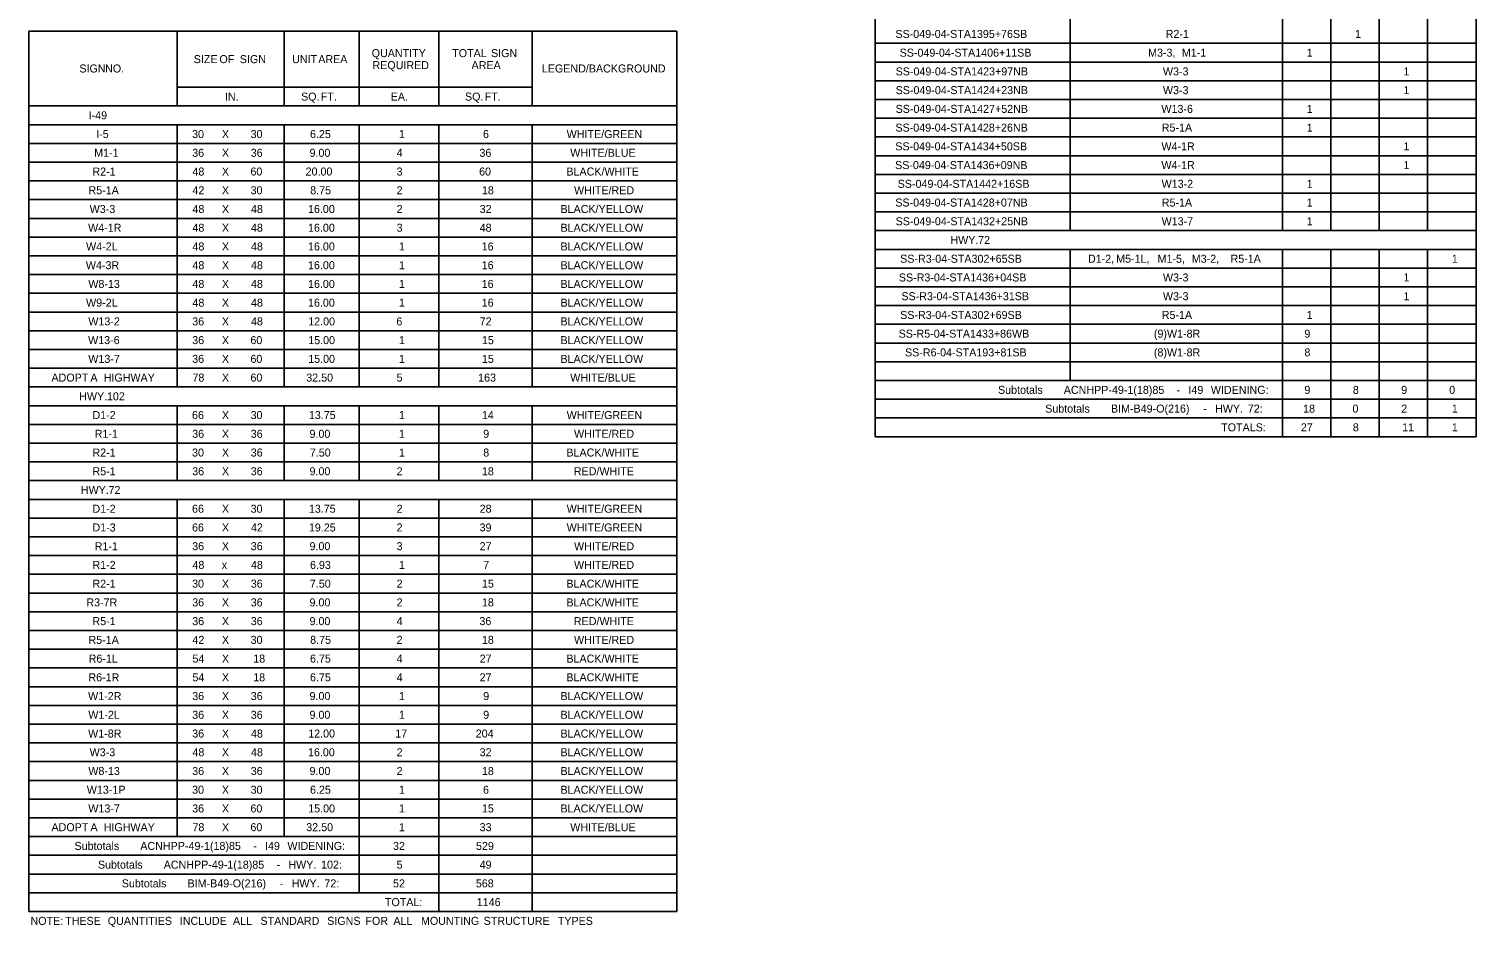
# Model space of a CAD drawing. Extents: x 1226613 to 1228135, y 151309 to 152326.
# Drawn here: x 1226615 to 1227428, y 151322 to 151827 of the extents above; entities that cross this region are included whole.
import ezdxf

# ---------------------------------------------------------------- set-up
doc = ezdxf.new("R2010")
doc.units = 0
doc.layers.add('R_Dimension', color=7, linetype='Continuous')

msp = doc.modelspace()

# ---------------------------------------------------------------- linework, layer by layer
at = {"layer": 'R_Dimension'}
for p, q in [((1227090.5, 151597.36), (1227090.5, 152039.62)), ((1227428.34, 151597.36), (1227428.34, 152039.62)), ((1227200.19, 151713.19), (1227200.19, 151986.97)), ((1227319.53, 151713.19), (1227319.53, 151986.97)), ((1227346.73, 151713.19), (1227346.73, 151986.97)), ((1227373.93, 151713.19), (1227373.93, 151986.97)), ((1227401.13, 151713.19), (1227401.13, 151986.97)), ((1226614.79, 151825.39), (1226978.96, 151825.39)), ((1226614.79, 151330.48), (1226614.79, 151825.39)), ((1226698.16, 151783.27), (1226698.16, 151825.39)), ((1226758.27, 151783.27), (1226758.27, 151825.39)), ((1226800.39, 151783.27), (1226800.39, 151825.39)), ((1226845.14, 151783.27), (1226845.14, 151825.39)), ((1226897.79, 151783.27), (1226897.79, 151825.39)), ((1226978.96, 151330.48), (1226978.96, 151825.39)), ((1227090.5, 151818.49), (1227428.34, 151818.49)), ((1227090.5, 151807.96), (1227428.34, 151807.96)), ((1226698.16, 151793.8), (1226897.79, 151793.8)), ((1227090.5, 151797.43), (1227428.34, 151797.43)), ((1226614.79, 151783.27), (1226978.96, 151783.27)), ((1226897.79, 151783.27), (1226978.96, 151783.27)), ((1227090.5, 151786.9), (1227428.34, 151786.9)), ((1227090.5, 151776.37), (1227428.34, 151776.37)), ((1226614.79, 151772.74), (1226978.96, 151772.74)), ((1226698.16, 151625.32), (1226698.16, 151772.74)), ((1226758.27, 151625.32), (1226758.27, 151772.74)), ((1226800.39, 151625.32), (1226800.39, 151772.74)), ((1226845.14, 151625.32), (1226845.14, 151772.74)), ((1226897.79, 151625.32), (1226897.79, 151772.74)), ((1226614.79, 151762.21), (1226978.96, 151762.21)), ((1227090.5, 151765.84), (1227428.34, 151765.84)), ((1226614.79, 151751.68), (1226978.96, 151751.68)), ((1227090.5, 151755.31), (1227428.34, 151755.31)), ((1227090.5, 151744.78), (1227428.34, 151744.78)), ((1226614.79, 151741.15), (1226978.96, 151741.15)), ((1227090.5, 151734.25), (1227428.34, 151734.25)), ((1226614.79, 151730.62), (1226978.96, 151730.62)), ((1226614.79, 151720.09), (1226978.96, 151720.09)), ((1227090.5, 151723.72), (1227428.34, 151723.72)), ((1226614.79, 151709.56), (1226978.96, 151709.56)), ((1227090.5, 151713.19), (1227428.34, 151713.19)), ((1227090.5, 151702.66), (1227428.34, 151702.66)), ((1227200.19, 151628.95), (1227200.19, 151702.66)), ((1227319.53, 151597.36), (1227319.53, 151702.66)), ((1227346.73, 151597.36), (1227346.73, 151702.66)), ((1227373.93, 151597.36), (1227373.93, 151702.66)), ((1227401.13, 151597.36), (1227401.13, 151702.66)), ((1226614.79, 151699.03), (1226978.96, 151699.03)), ((1226614.79, 151688.5), (1226978.96, 151688.5)), ((1227090.5, 151692.13), (1227428.34, 151692.13)), ((1226614.79, 151677.97), (1226978.96, 151677.97)), ((1227090.5, 151681.6), (1227428.34, 151681.6)), ((1227090.5, 151671.07), (1227428.34, 151671.07)), ((1226614.79, 151667.44), (1226978.96, 151667.44)), ((1227090.5, 151660.54), (1227428.34, 151660.54)), ((1226614.79, 151656.91), (1226978.96, 151656.91)), ((1226614.79, 151646.38), (1226978.96, 151646.38)), ((1227090.5, 151650.01), (1227428.34, 151650.01)), ((1227090.5, 151639.48), (1227428.34, 151639.48)), ((1226614.79, 151635.85), (1226978.96, 151635.85)), ((1227090.5, 151628.95), (1227428.34, 151628.95)), ((1226614.79, 151625.32), (1226978.96, 151625.32)), ((1226614.79, 151614.79), (1226978.96, 151614.79)), ((1226698.16, 151572.67), (1226698.16, 151614.79)), ((1226758.27, 151572.67), (1226758.27, 151614.79)), ((1226800.39, 151572.67), (1226800.39, 151614.79)), ((1226845.14, 151572.67), (1226845.14, 151614.79)), ((1226897.79, 151572.67), (1226897.79, 151614.79)), ((1227090.5, 151618.42), (1227428.34, 151618.42)), ((1226614.79, 151604.26), (1226978.96, 151604.26)), ((1227090.5, 151607.89), (1227428.34, 151607.89)), ((1227090.5, 151597.36), (1227428.34, 151597.36)), ((1226614.79, 151593.73), (1226978.96, 151593.73)), ((1226614.79, 151583.2), (1226978.96, 151583.2)), ((1226614.79, 151572.67), (1226978.96, 151572.67)), ((1226614.79, 151562.14), (1226978.96, 151562.14)), ((1226698.16, 151372.6), (1226698.16, 151562.14)), ((1226758.27, 151372.6), (1226758.27, 151562.14)), ((1226800.39, 151341.01), (1226800.39, 151562.14)), ((1226845.14, 151330.48), (1226845.14, 151562.14)), ((1226897.79, 151330.48), (1226897.79, 151562.14)), ((1226614.79, 151551.61), (1226978.96, 151551.61)), ((1226614.79, 151541.08), (1226978.96, 151541.08)), ((1226614.79, 151530.55), (1226978.96, 151530.55)), ((1226614.79, 151520.02), (1226978.96, 151520.02)), ((1226614.79, 151509.49), (1226978.96, 151509.49)), ((1226614.79, 151498.96), (1226978.96, 151498.96)), ((1226614.79, 151488.43), (1226978.96, 151488.43)), ((1226614.79, 151477.9), (1226978.96, 151477.9)), ((1226614.79, 151467.37), (1226978.96, 151467.37)), ((1226614.79, 151456.84), (1226978.96, 151456.84)), ((1226614.79, 151446.31), (1226978.96, 151446.31)), ((1226614.79, 151435.78), (1226978.96, 151435.78)), ((1226614.79, 151425.25), (1226978.96, 151425.25)), ((1226614.79, 151414.72), (1226978.96, 151414.72)), ((1226614.79, 151404.19), (1226978.96, 151404.19)), ((1226614.79, 151393.66), (1226978.96, 151393.66)), ((1226614.79, 151383.13), (1226978.96, 151383.13)), ((1226614.79, 151372.6), (1226978.96, 151372.6)), ((1226614.79, 151362.07), (1226978.96, 151362.07)), ((1226614.79, 151351.54), (1226978.96, 151351.54)), ((1226614.79, 151341.01), (1226978.96, 151341.01)), ((1226614.79, 151330.48), (1226978.96, 151330.48))]:
    msp.add_line(p, q, dxfattribs=at)

# ---------------------------------------------------------------- texts
for s, p in [('SS-049-04-STA1395+76SB', (1227101.92, 151821.5)), ('R2-1', (1227253.87, 151821.5)), ('1', (1227360.33, 151821.5)), ('QUANTITY', (1226807.49, 151810.72)), ('TOTAL', (1226852.75, 151810.72)), (' SIGN', (1226872.88, 151810.72)), ('SS-049-04-STA1406+11SB', (1227104.29, 151810.97)), ('M3-3,', (1227243.96, 151810.97)), (' M1-1', (1227261.26, 151810.97)), ('1', (1227333.13, 151810.97)), ('SIZE', (1226707.45, 151807.34)), (' OF', (1226720.2, 151807.34)), (' SIGN', (1226731.68, 151807.34)), ('UNIT', (1226762.76, 151807.34)), (' AREA', (1226775.77, 151807.34)), ('REQUIRED', (1226807.93, 151803.97)), ('AREA', (1226863.65, 151803.97)), ('LEGEND/BACKGROUND', (1226903.13, 151802.08)), ('SIGN', (1226643.15, 151802.08)), (' NO.', (1226655.94, 151802.08)), ('SS-049-04-STA1423+97NB', (1227102.03, 151800.44)), ('W3-3', (1227252.31, 151800.44)), ('1', (1227387.53, 151800.44)), ('IN.', (1226724.99, 151786.28)), ('SQ.', (1226767.79, 151786.28)), (' FT.', (1226777.22, 151786.28)), ('EA.', (1226818.19, 151786.28)), ('SQ.', (1226859.93, 151786.28)), (' FT.', (1226869.36, 151786.28)), ('SS-049-04-STA1424+23NB', (1227102.03, 151789.91)), ('W3-3', (1227252.31, 151789.91)), ('1', (1227387.53, 151789.91)), ('SS-049-04-STA1427+52NB', (1227102.03, 151779.38)), ('W13-6', (1227251.44, 151779.38)), ('1', (1227333.13, 151779.38)), ('I-49', (1226648.33, 151775.75)), ('I-5', (1226652.61, 151765.22)), ('30', (1226706.51, 151765.22)), ('X', (1226723.28, 151765.22)), ('30', (1226739.42, 151765.22)), ('6.25', (1226772.81, 151765.22)), ('1', (1226822.76, 151765.22)), ('6', (1226870.06, 151765.22)), ('WHITE/GREEN', (1226917.1, 151765.22)), ('SS-049-04-STA1428+26NB', (1227101.92, 151768.85)), ('R5-1A', (1227251.65, 151768.85)), ('1', (1227333.13, 151768.85)), ('M1-1', (1226651.48, 151754.69)), ('36', (1226706.58, 151754.69)), ('X', (1226723.28, 151754.69)), ('36', (1226739.49, 151754.69)), ('9.00', (1226772.54, 151754.69)), ('4', (1226821.49, 151754.69)), ('36', (1226868.04, 151754.69)), ('WHITE/BLUE', (1226919.1, 151754.69)), ('SS-049-04-STA1434+50SB', (1227101.85, 151758.32)), ('W4-1R', (1227251.44, 151758.32)), ('1', (1227387.53, 151758.32)), ('SS-049-04-STA1436+09NB', (1227101.74, 151747.79)), ('W4-1R', (1227251.44, 151747.79)), ('1', (1227387.53, 151747.79)), ('R2-1', (1226650.49, 151744.16)), ('48', (1226706.71, 151744.16)), ('X', (1226723.28, 151744.16)), ('60', (1226739.31, 151744.16)), ('20.00', (1226770.34, 151744.16)), ('3', (1226821.49, 151744.16)), ('60', (1226867.87, 151744.16)), ('BLACK/WHITE', (1226916.94, 151744.16)), ('SS-049-04-STA1442+16SB', (1227103.19, 151737.26)), ('W13-2', (1227251.56, 151737.26)), ('1', (1227333.13, 151737.26)), ('R5-1A', (1226648.27, 151733.63)), ('42', (1226706.71, 151733.63)), ('X', (1226723.28, 151733.63)), ('30', (1226739.42, 151733.63)), ('8.75', (1226772.91, 151733.63)), ('2', (1226821.49, 151733.63)), ('18', (1226869.44, 151733.63)), ('WHITE/RED', (1226921.24, 151733.63)), ('W3-3', (1226648.93, 151723.1)), ('48', (1226706.71, 151723.1)), ('X', (1226723.28, 151723.1)), ('48', (1226739.61, 151723.1)), ('16.00', (1226771.69, 151723.1)), ('2', (1226821.49, 151723.1)), ('32', (1226868.17, 151723.1)), ('BLACK/YELLOW', (1226913.61, 151723.1)), ('SS-049-04-STA1428+07NB', (1227101.85, 151726.73)), ('R5-1A', (1227251.65, 151726.73)), ('1', (1227333.13, 151726.73)), ('BLACK/YELLOW', (1226913.61, 151712.57)), ('SS-049-04-STA1432+25NB', (1227102.03, 151716.2)), ('W13-7', (1227251.56, 151716.2)), ('1', (1227333.13, 151716.2)), ('W4-1R', (1226648.06, 151712.57)), ('48', (1226706.71, 151712.57)), ('X', (1226723.28, 151712.57)), ('48', (1226739.61, 151712.57)), ('16.00', (1226771.69, 151712.57)), ('3', (1226821.49, 151712.57)), ('48', (1226868.17, 151712.57)), ('HWY.', (1227132.85, 151705.67)), (' 72', (1227146.74, 151705.67)), ('W4-2L', (1226646.91, 151702.04)), ('48', (1226706.71, 151702.04)), ('X', (1226723.28, 151702.04)), ('48', (1226739.61, 151702.04)), ('16.00', (1226771.69, 151702.04)), ('1', (1226822.76, 151702.04)), ('16', (1226869.32, 151702.04)), ('BLACK/YELLOW', (1226913.61, 151702.04)), ('W4-3R', (1226646.79, 151691.51)), ('48', (1226706.71, 151691.51)), ('X', (1226723.28, 151691.51)), ('48', (1226739.61, 151691.51)), ('16.00', (1226771.69, 151691.51)), ('1', (1226822.76, 151691.51)), ('16', (1226869.32, 151691.51)), ('BLACK/YELLOW', (1226913.61, 151691.51)), ('SS-R3-04-STA302+65SB', (1227104.58, 151695.14)), ('D1-2,', (1227210.16, 151695.14)), (' M5-1L,', (1227224.33, 151695.14)), (' M1-5,', (1227247.61, 151695.14)), (' M3-2,', (1227266.85, 151695.14)), (' R5-1A', (1227288.65, 151695.14)), ('1', (1227414.73, 151695.14)), ('W8-13', (1226648.18, 151680.98)), ('48', (1226706.71, 151680.98)), ('X', (1226723.28, 151680.98)), ('48', (1226739.61, 151680.98)), ('16.00', (1226771.69, 151680.98)), ('1', (1226822.76, 151680.98)), ('16', (1226869.32, 151680.98)), ('BLACK/YELLOW', (1226913.61, 151680.98)), ('SS-R3-04-STA1436+04SB', (1227103.83, 151684.61)), ('W3-3', (1227252.31, 151684.61)), ('1', (1227387.53, 151684.61)), ('SS-R3-04-STA1436+31SB', (1227105.29, 151674.08)), ('W3-3', (1227252.31, 151674.08)), ('1', (1227387.53, 151674.08)), ('W9-2L', (1226646.91, 151670.45)), ('48', (1226706.71, 151670.45)), ('X', (1226723.28, 151670.45)), ('48', (1226739.61, 151670.45)), ('16.00', (1226771.69, 151670.45)), ('1', (1226822.76, 151670.45)), ('16', (1226869.32, 151670.45)), ('BLACK/YELLOW', (1226913.61, 151670.45)), ('W13-2', (1226648.18, 151659.92)), ('36', (1226706.58, 151659.92)), ('X', (1226723.28, 151659.92)), ('48', (1226739.61, 151659.92)), ('12.00', (1226771.8, 151659.92)), ('6', (1226821.36, 151659.92)), ('72', (1226868.17, 151659.92)), ('BLACK/YELLOW', (1226913.61, 151659.92)), ('SS-R3-04-STA302+69SB', (1227104.58, 151663.55)), ('R5-1A', (1227251.65, 151663.55)), ('1', (1227333.13, 151663.55)), ('W13-6', (1226648.06, 151649.39)), ('36', (1226706.58, 151649.39)), ('X', (1226723.28, 151649.39)), ('60', (1226739.31, 151649.39)), ('15.00', (1226771.8, 151649.39)), ('1', (1226822.76, 151649.39)), ('15', (1226869.44, 151649.39)), ('BLACK/YELLOW', (1226913.61, 151649.39)), ('SS-R5-04-STA1433+86WB', (1227103.73, 151653.02)), ('(9)W1-8R', (1227247.22, 151653.02)), ('9', (1227331.83, 151653.02)), ('SS-R6-04-STA193+81SB', (1227107.3, 151642.49)), ('(8)W1-8R', (1227247.22, 151642.49)), ('8', (1227331.85, 151642.49)), ('W13-7', (1226648.18, 151638.86)), ('36', (1226706.58, 151638.86)), ('X', (1226723.28, 151638.86)), ('60', (1226739.31, 151638.86)), ('15.00', (1226771.8, 151638.86)), ('1', (1226822.76, 151638.86)), ('15', (1226869.44, 151638.86)), ('BLACK/YELLOW', (1226913.61, 151638.86)), ('ADOPT', (1226627.46, 151628.33)), (' A', (1226647.69, 151628.33)), (' HIGHWAY', (1226655.13, 151628.33)), ('78', (1226706.71, 151628.33)), ('X', (1226723.28, 151628.33)), ('60', (1226739.31, 151628.33)), ('32.50', (1226770.7, 151628.33)), ('5', (1226821.49, 151628.33)), ('163', (1226867.32, 151628.33)), ('WHITE/BLUE', (1226919.1, 151628.33)), ('HWY.', (1226643.06, 151617.8)), (' 102', (1226656.95, 151617.8)), ('Subtotals', (1227159.59, 151621.43)), (' ACNHPP-49-1(18)85', (1227194.88, 151621.43)), (' -', (1227258.27, 151621.43)), (' I49', (1227264.96, 151621.43)), (' WIDENING:', (1227277.58, 151621.43)), ('9', (1227331.83, 151621.43)), ('8', (1227359.05, 151621.43)), ('9', (1227386.24, 151621.43)), ('0', (1227413.26, 151621.43)), ('D1-2', (1226650.49, 151607.27)), ('66', (1226706.48, 151607.27)), ('X', (1226723.28, 151607.27)), ('30', (1226739.42, 151607.27)), ('13.75', (1226772.17, 151607.27)), ('1', (1226822.76, 151607.27)), ('14', (1226869.44, 151607.27)), ('WHITE/GREEN', (1226917.1, 151607.27)), ('Subtotals', (1227186.12, 151610.9)), (' BIM-B49-O(216)', (1227221.42, 151610.9)), (' -', (1227273.25, 151610.9)), (' HWY.', (1227279.95, 151610.9)), (' 72:', (1227298.34, 151610.9)), ('18', (1227331.11, 151610.9)), ('0', (1227358.86, 151610.9)), ('2', (1227386.26, 151610.9)), ('1', (1227414.73, 151610.9)), ('TOTALS:', (1227285.05, 151600.37)), ('27', (1227329.83, 151600.37)), ('8', (1227359.05, 151600.37)), ('11', (1227386.79, 151600.37)), ('1', (1227414.73, 151600.37)), ('R1-1', (1226651.76, 151596.74)), ('36', (1226706.58, 151596.74)), ('X', (1226723.28, 151596.74)), ('36', (1226739.49, 151596.74)), ('9.00', (1226772.54, 151596.74)), ('1', (1226822.76, 151596.74)), ('9', (1226870.17, 151596.74)), ('WHITE/RED', (1226921.24, 151596.74)), ('R2-1', (1226650.49, 151586.21)), ('30', (1226706.51, 151586.21)), ('X', (1226723.28, 151586.21)), ('36', (1226739.49, 151586.21)), ('7.50', (1226772.72, 151586.21)), ('1', (1226822.76, 151586.21)), ('8', (1226870.19, 151586.21)), ('BLACK/WHITE', (1226916.94, 151586.21)), ('R5-1', (1226650.49, 151575.68)), ('36', (1226706.58, 151575.68)), ('X', (1226723.28, 151575.68)), ('36', (1226739.49, 151575.68)), ('9.00', (1226772.54, 151575.68)), ('2', (1226821.49, 151575.68)), ('18', (1226869.44, 151575.68)), ('RED/WHITE', (1226921.15, 151575.68)), ('HWY.', (1226643.99, 151565.15)), (' 72', (1226657.88, 151565.15)), ('D1-2', (1226650.49, 151554.62)), ('66', (1226706.48, 151554.62)), ('X', (1226723.28, 151554.62)), ('30', (1226739.42, 151554.62)), ('13.75', (1226772.17, 151554.62)), ('2', (1226821.49, 151554.62)), ('28', (1226868.17, 151554.62)), ('WHITE/GREEN', (1226917.1, 151554.62)), ('D1-3', (1226650.49, 151544.09)), ('66', (1226706.48, 151544.09)), ('X', (1226723.28, 151544.09)), ('42', (1226739.61, 151544.09)), ('19.25', (1226772.17, 151544.09)), ('2', (1226821.49, 151544.09)), ('39', (1226868.15, 151544.09)), ('WHITE/GREEN', (1226917.1, 151544.09)), ('WHITE/RED', (1226921.24, 151533.56)), ('R1-1', (1226651.76, 151533.56)), ('36', (1226706.58, 151533.56)), ('X', (1226723.28, 151533.56)), ('36', (1226739.49, 151533.56)), ('9.00', (1226772.54, 151533.56)), ('3', (1226821.49, 151533.56)), ('27', (1226868.17, 151533.56)), ('R1-2', (1226650.49, 151523.03)), ('48', (1226706.71, 151523.03)), ('x', (1226723.21, 151523.03)), ('48', (1226739.61, 151523.03)), ('6.93', (1226772.81, 151523.03)), ('1', (1226822.76, 151523.03)), ('7', (1226870.19, 151523.03)), ('WHITE/RED', (1226921.24, 151523.03)), ('R2-1', (1226650.49, 151512.5)), ('30', (1226706.51, 151512.5)), ('X', (1226723.28, 151512.5)), ('36', (1226739.49, 151512.5)), ('7.50', (1226772.72, 151512.5)), ('2', (1226821.49, 151512.5)), ('15', (1226869.44, 151512.5)), ('BLACK/WHITE', (1226916.94, 151512.5)), ('R3-7R', (1226647.07, 151501.97)), ('36', (1226706.58, 151501.97)), ('X', (1226723.28, 151501.97)), ('36', (1226739.49, 151501.97)), ('9.00', (1226772.54, 151501.97)), ('2', (1226821.49, 151501.97)), ('18', (1226869.44, 151501.97)), ('BLACK/WHITE', (1226916.94, 151501.97)), ('R5-1', (1226650.49, 151491.44)), ('36', (1226706.58, 151491.44)), ('X', (1226723.28, 151491.44)), ('36', (1226739.49, 151491.44)), ('9.00', (1226772.54, 151491.44)), ('4', (1226821.49, 151491.44)), ('36', (1226868.04, 151491.44)), ('RED/WHITE', (1226921.15, 151491.44)), ('R5-1A', (1226648.27, 151480.91)), ('42', (1226706.71, 151480.91)), ('X', (1226723.28, 151480.91)), ('30', (1226739.42, 151480.91)), ('8.75', (1226772.91, 151480.91)), ('2', (1226821.49, 151480.91)), ('18', (1226869.44, 151480.91)), ('WHITE/RED', (1226921.24, 151480.91)), ('R6-1L', (1226648.36, 151470.38)), ('54', (1226706.71, 151470.38)), ('X', (1226723.28, 151470.38)), ('18', (1226740.89, 151470.38)), ('6.75', (1226772.81, 151470.38)), ('4', (1226821.49, 151470.38)), ('27', (1226868.17, 151470.38)), ('BLACK/WHITE', (1226916.94, 151470.38)), ('R6-1R', (1226648.24, 151459.85)), ('54', (1226706.71, 151459.85)), ('X', (1226723.28, 151459.85)), ('18', (1226740.89, 151459.85)), ('6.75', (1226772.81, 151459.85)), ('4', (1226821.49, 151459.85)), ('27', (1226868.17, 151459.85)), ('BLACK/WHITE', (1226916.94, 151459.85)), ('W1-2R', (1226648.06, 151449.32)), ('36', (1226706.58, 151449.32)), ('X', (1226723.28, 151449.32)), ('36', (1226739.49, 151449.32)), ('9.00', (1226772.54, 151449.32)), ('1', (1226822.76, 151449.32)), ('9', (1226870.17, 151449.32)), ('BLACK/YELLOW', (1226913.61, 151449.32)), ('W1-2L', (1226648.18, 151438.79)), ('36', (1226706.58, 151438.79)), ('X', (1226723.28, 151438.79)), ('36', (1226739.49, 151438.79)), ('9.00', (1226772.54, 151438.79)), ('1', (1226822.76, 151438.79)), ('9', (1226870.17, 151438.79)), ('BLACK/YELLOW', (1226913.61, 151438.79)), ('W1-8R', (1226648.06, 151428.26)), ('36', (1226706.58, 151428.26)), ('X', (1226723.28, 151428.26)), ('48', (1226739.61, 151428.26)), ('12.00', (1226771.8, 151428.26)), ('17', (1226820.74, 151428.26)), ('204', (1226865.97, 151428.26)), ('BLACK/YELLOW', (1226913.61, 151428.26)), ('W3-3', (1226648.93, 151417.73)), ('48', (1226706.71, 151417.73)), ('X', (1226723.28, 151417.73)), ('48', (1226739.61, 151417.73)), ('16.00', (1226771.69, 151417.73)), ('2', (1226821.49, 151417.73)), ('32', (1226868.17, 151417.73)), ('BLACK/YELLOW', (1226913.61, 151417.73)), ('W8-13', (1226648.18, 151407.2)), ('36', (1226706.58, 151407.2)), ('X', (1226723.28, 151407.2)), ('36', (1226739.49, 151407.2)), ('9.00', (1226772.54, 151407.2)), ('2', (1226821.49, 151407.2)), ('18', (1226869.44, 151407.2)), ('BLACK/YELLOW', (1226913.61, 151407.2)), ('W13-1P', (1226647.32, 151396.67)), ('30', (1226706.51, 151396.67)), ('X', (1226723.28, 151396.67)), ('30', (1226739.42, 151396.67)), ('6.25', (1226772.81, 151396.67)), ('1', (1226822.76, 151396.67)), ('6', (1226870.06, 151396.67)), ('BLACK/YELLOW', (1226913.61, 151396.67)), ('W13-7', (1226648.18, 151386.14)), ('36', (1226706.58, 151386.14)), ('X', (1226723.28, 151386.14)), ('60', (1226739.31, 151386.14)), ('15.00', (1226771.8, 151386.14)), ('1', (1226822.76, 151386.14)), ('15', (1226869.44, 151386.14)), ('BLACK/YELLOW', (1226913.61, 151386.14)), ('ADOPT', (1226627.46, 151375.61)), (' A', (1226647.69, 151375.61)), (' HIGHWAY', (1226655.13, 151375.61)), ('78', (1226706.71, 151375.61)), ('X', (1226723.28, 151375.61)), ('60', (1226739.31, 151375.61)), ('32.50', (1226770.7, 151375.61)), ('1', (1226822.76, 151375.61)), ('33', (1226868.17, 151375.61)), ('WHITE/BLUE', (1226919.1, 151375.61)), ('Subtotals', (1226640.45, 151365.08)), (' ACNHPP-49-1(18)85', (1226675.74, 151365.08)), (' I49', (1226745.82, 151365.08)), (' WIDENING:', (1226758.44, 151365.08)), ('32', (1226819.47, 151365.08)), ('529', (1226866.13, 151365.08)), (' -', (1226739.13, 151365.08)), ('Subtotals', (1226653.59, 151354.55)), (' ACNHPP-49-1(18)85', (1226688.88, 151354.55)), (' -', (1226752.27, 151354.55)), (' HWY.', (1226758.97, 151354.55)), (' 102:', (1226777.36, 151354.55)), ('5', (1226821.49, 151354.55)), ('49', (1226868.15, 151354.55)), ('Subtotals', (1226666.98, 151344.02)), (' BIM-B49-O(216)', (1226702.28, 151344.02)), (' -', (1226754.11, 151344.02)), (' HWY.', (1226760.81, 151344.02)), (' 72:', (1226779.2, 151344.02)), ('52', (1226819.47, 151344.02)), ('568', (1226866.04, 151344.02)), ('TOTAL:', (1226814.92, 151333.49)), ('1146', (1226866.56, 151333.49)), ('NOTE:', (1226615.67, 151322.96)), (' THESE', (1226633.46, 151322.96)), (' QUANTITIES', (1226657.45, 151322.96)), (' INCLUDE', (1226697.95, 151322.96)), (' ALL', (1226727.82, 151322.96)), (' STANDARD', (1226743.3, 151322.96)), (' SIGNS', (1226780.79, 151322.96)), (' FOR', (1226802.3, 151322.96)), (' ALL', (1226818.03, 151322.96)), (' MOUNTING', (1226833.51, 151322.96)), (' STRUCTURE', (1226868.74, 151322.96)), (' TYPES', (1226910.44, 151322.96))]:
    msp.add_text(s, height=4.5, dxfattribs=at).set_placement(p)

doc.saveas('drawing.dxf')
